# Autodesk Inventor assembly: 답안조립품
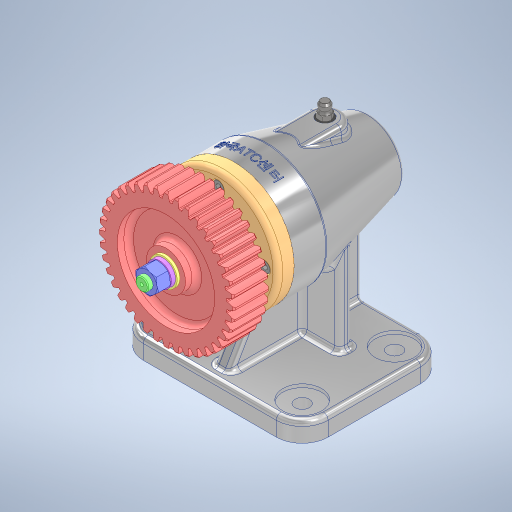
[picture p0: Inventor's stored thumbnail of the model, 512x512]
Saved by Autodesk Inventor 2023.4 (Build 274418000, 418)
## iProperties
Created: 2024-12
Part Number: 답안조립품
Document SubType Name: Assembly
Designer: EDU
Author: EDU
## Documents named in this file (15)
- C:\Users\EDU\Desktop\741204V1021\답안조립품.iam
- C:\Users\EDU\Desktop\741204V1021\본체.ipt
- C:\Users\EDU\Desktop\741204V1021\앵귤러 볼 베어링 7003A\앵귤러 볼 베어링 7003A.ipt
- C:\Users\EDU\Desktop\741204V1021\축\축.ipt
- C:\Users\EDU\Desktop\741204V1021\앵귤러 볼 제어링 7204A\앵귤러 볼 제어링 7204A.ipt
- C:\Users\EDU\Desktop\741204V1021\커버\커버.ipt
- C:\Users\EDU\Desktop\741204V1021\오일 실 20 32 8\오일 실 20 32 8.ipt
- C:\Users\EDU\Desktop\741204V1021\육각 소켓 머리 볼트 M4x10\육각 소켓 머리 볼트 M4x10.ipt
- C:\Users\EDU\Desktop\741204V1021\평행 키 4x4x14\평행 키 4x4x14.ipt
- C:\Users\EDU\Desktop\741204V1021\스퍼기어\스퍼기어.ipt
- C:\Users\EDU\Desktop\741204V1021\평와셔 M8\평와셔 M8.ipt
- C:\Users\EDU\Desktop\741204V1021\스프링 와셔 M8\스프링 와셔 M8.ipt
- C:\Users\EDU\Desktop\741204V1021\육각 너트 M8\육각 너트 M8.ipt
- C:\Users\EDU\Desktop\741204V1021\실링\실링.ipt
- C:\Users\EDU\Desktop\741204V1021\그리스 니플 M6x0.75\그리스 니플 M6x0.75.ipt
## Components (1 placed, 1 different names)
1. 그리스 니플 M6x0.75:1
